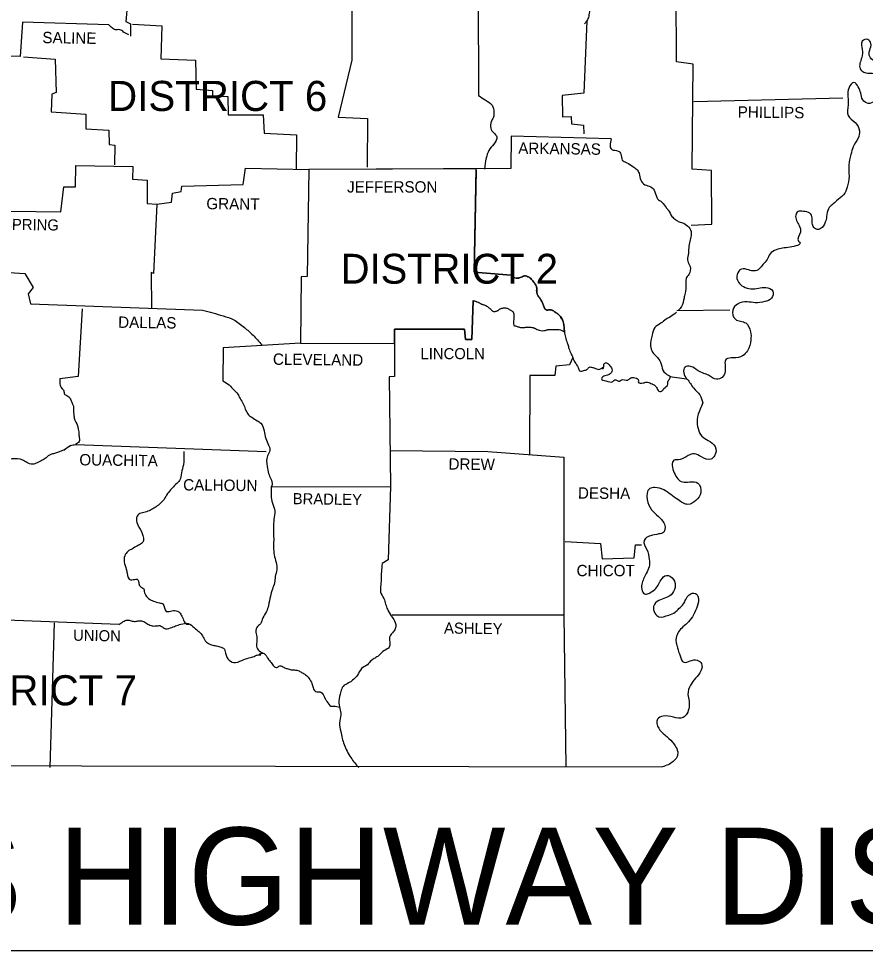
# Model space of a CAD drawing. Extents: x -42408 to 34530, y -43140 to 20491.
# Drawn here: x 2569 to 4174, y -23266 to -21499 of the extents above; entities that cross this region are included whole.
import ezdxf

# ---------------------------------------------------------------- set-up
doc = ezdxf.new("R2010")
doc.units = 0
for name, color, linetype in [('1', 7, 'Continuous'), ('2', 7, 'Continuous'), ('3', 7, 'Continuous'), ('S_MISC_BOUNDARY', 7, 'Continuous')]:
    doc.layers.add(name, color=color, linetype=linetype)

msp = doc.modelspace()

# ---------------------------------------------------------------- linework, layer by layer
at = {"layer": '1'}
msp.add_line((3816.9, -22053), (3917, -22051.5), dxfattribs=at)
for points in [[(3368.8, -21361.6), (3369.8, -21451.2), (3440.4, -21452.7), (3440.9, -21645)], [(3171, -21384.6), (3200.1, -21386.6), (3200.6, -21577.9), (3174.5, -21686.5), (3230.1, -21689), (3229.6, -21781.2)], [(2939.2, -21434.7), (2903.2, -21430.7), (2904.7, -21444.2), (2839.1, -21446.7), (2837.1, -21466.2), (2775.5, -21469.7), (2772, -21504.8), (2781, -21509.3), (2781, -21532.3)], [(3843.9, -21891.3), (3883, -21888.8), (3882.5, -21787.2), (3845.9, -21784.7), (3847.9, -21585.9), (3816.4, -21581.4), (3815.4, -21447.7), (4242.5, -21444.7)], [(2740, -21511.3), (2576.3, -21506.3), (2571.7, -21570.9), (2371.5, -21569.9), (2370.5, -21591.4)], [(2784.5, -21509.8), (2840.6, -21513.3), (2838.6, -21575.9), (2904.2, -21578.4), (2905.2, -21633), (2936.2, -21635.5), (2936.2, -21645), (2965.3, -21647), (2966.3, -21682), (3032.4, -21682), (3034.4, -21716.6), (3095.4, -21719.6), (3094.9, -21784.7)], [(3646.2, -21503.3), (3640.2, -21640.5), (3599.1, -21645), (3600.1, -21685.5), (3616.6, -21685), (3617.1, -21699), (3639.7, -21701.5), (3640.2, -21718.1)], [(2577.8, -21571.9), (2638.3, -21576.4), (2640.3, -21639.5), (2631.8, -21642.5), (2630.8, -21676), (2696.4, -21680.5), (2696.4, -21708.1), (2740, -21710.6), (2740.5, -21738.1), (2751, -21739.6), (2750.5, -21776.6)], [(3848.9, -21656.5), (4131.3, -21649.5)], [(3692.2, -21727.1), (3503, -21722.1), (3502, -21783.7), (3119, -21785.2)], [(2362.5, -21861.8), (2648.8, -21865.8), (2654.4, -21818.2), (2676.9, -21818.2), (2677.4, -21778.1), (2785.5, -21779.7), (2784.5, -21803.7), (2812.6, -21805.7), (2812.6, -21849.7), (2830.6, -21851.2)], [(2830.6, -21851.2), (2858.6, -21847.2), (2860.6, -21830.2), (2877.2, -21827.2), (2878.2, -21817.2), (2994.8, -21813.7), (2999.3, -21783.2), (3119, -21785.2)], [(3119, -21786.2), (3116, -21988.4), (3104.5, -21988.9), (3103, -22114.6)], [(3436.4, -21786.7), (3432.4, -21980.4), (3502, -21985.9)], [(2830.6, -21851.2), (2824.6, -21982.4), (2820.1, -21980.9), (2820.6, -22049)], [(2303.4, -21995.4), (2302.4, -21967.9), (2310.4, -21967.4), (2315.4, -21902.8), (2392.5, -21907.8), (2390.5, -21947.4), (2490.1, -21952.9), (2490.6, -21976.9), (2580.8, -21982.4), (2596.3, -22009.5), (2586.8, -22021.5), (2591.3, -22040), (2917.7, -22052)], [(2689.4, -22049.5), (2681.9, -22178.2), (2647.3, -22182.2)], [(3430.9, -22034), (3427.9, -22107.6), (3416.4, -22107.6), (3414.4, -22088.1), (3281.2, -22088.1), (3281.2, -22116.1)], [(3030.9, -22119.1), (2956.8, -22123.6), (2956.3, -22186.2)], [(3103, -22114.6), (3029.9, -22119.1)], [(3103, -22114.6), (3280.2, -22115.6)], [(3281.2, -22115.6), (3281.7, -22178.2), (3271.2, -22178.7), (3274.2, -22386.5)], [(3619.6, -22142.1), (3613.6, -22155.7), (3587.1, -22158.2), (3585.6, -22176.2), (3538, -22176.2), (3537.5, -22325.9)], [(3675.7, -22164.2), (3677.2, -22162.7), (3678.7, -22161.2), (3678.7, -22161.2)], [(2676.9, -22306.9), (2884.2, -22314.4), (3037.9, -22320.4)], [(3272.7, -22318.4), (3458.4, -22319.9), (3602.6, -22330.9)], [(3602.6, -22330.9), (3602.6, -22630.3), (3606.6, -22918.2)], [(3047.9, -22387), (3274.2, -22386.5)], [(3274.2, -22386.5), (3269.2, -22525.6), (3258.2, -22532.7)], [(3605.1, -22490.6), (3672.2, -22494.6), (3675.2, -22523.6), (3735.8, -22521.6), (3738.3, -22497.1), (3749.8, -22497.1)], [(1953.4, -22510.1), (1954.4, -22915.2), (3789.4, -22918.2)], [(2759, -22648.3), (2545.2, -22640.3), (2544.2, -22589.7)], [(3277.2, -22629.8), (3602.6, -22629.8)], [(2636.3, -22644.8), (2628.3, -22919.7)]]:
    msp.add_lwpolyline(points, dxfattribs=at)
for points in [[(3640.7, -21455.2), (3638.7, -21465.2), (3642.7, -21475.7), (3649.7, -21479.3), (3650.7, -21489.3), (3648.2, -21499.3), (3646.2, -21503.3), (3641.7, -21509.3)], [(2777.5, -21529.8), (2768, -21524.8), (2760.5, -21520.3), (2752.5, -21520.8), (2746, -21516.8), (2740, -21511.3)], [(4210.9, -21565.9), (4199.4, -21580.4), (4182.4, -21571.4), (4182.4, -21559.4), (4184.9, -21546.8), (4178.9, -21538.8), (4168.4, -21542.3), (4168.4, -21557.9), (4167.4, -21572.9), (4164.4, -21594.4), (4171.4, -21600.9), (4187.4, -21602.9), (4198.9, -21605.9), (4205.9, -21617.4), (4205.4, -21631.5), (4199.9, -21645), (4191.9, -21656), (4179.4, -21660), (4169.4, -21653.5), (4165.4, -21640.5), (4160.9, -21628.9), (4152.4, -21620.4), (4143.3, -21630), (4141.3, -21647.5), (4141.8, -21662.5), (4141.8, -21683), (4154.9, -21696.5), (4162.9, -21712.1), (4160.4, -21726.1), (4150.9, -21742.6), (4146.8, -21757.1), (4142.8, -21776.6), (4143.3, -21798.2), (4139.8, -21819.2), (4132.8, -21833.2), (4119.8, -21844.7), (4111.3, -21852.2), (4104.3, -21859.8), (4100.8, -21874.8), (4098.3, -21885.3), (4088.8, -21897.8), (4081.3, -21898.8), (4075.3, -21893.8), (4073.2, -21885.3), (4073.2, -21876.8), (4069.2, -21868.3), (4056.7, -21864.8), (4046.7, -21865.3), (4042.2, -21872.3), (4048.7, -21891.8), (4051.2, -21904.3), (4047.7, -21921.3), (4049.7, -21923.3), (4031.7, -21932.9), (4017.2, -21934.4), (4005.2, -21937.9), (3993.6, -21945.4), (3988.1, -21956.4), (3980.1, -21965.4), (3973.1, -21973.9), (3963.6, -21977.9), (3953.1, -21975.9), (3939.1, -21974.4), (3931.1, -21984.4), (3933.6, -21998.9), (3943.1, -22007.5), (3957.1, -22011.5), (3971.6, -22010.5), (3985.6, -22009), (3998.6, -22016), (3996.1, -22029.5), (3983.6, -22036), (3965.1, -22038), (3950.1, -22036.5), (3932.1, -22040.5), (3923, -22052), (3928.1, -22069.5), (3947.6, -22076.5), (3956.6, -22093.1), (3957.1, -22108.6), (3950.6, -22129.1), (3941.6, -22138.6), (3924, -22142.6), (3910.5, -22145.1), (3908.5, -22168.2), (3902.5, -22179.7), (3892, -22183.2), (3877, -22175.7), (3868, -22172.2), (3857, -22167.2), (3842.9, -22158.7), (3832.4, -22160.2), (3835.4, -22182.2), (3836.4, -22183.2), (3848.4, -22199.7), (3860.5, -22212.7), (3866, -22228.2)], [(3440.9, -21645), (3453.4, -21653.5), (3466.4, -21663.5), (3469.9, -21677), (3468.9, -21686.5), (3464.9, -21694.5), (3463.9, -21707.1), (3469.9, -21716.1), (3475.5, -21723.6), (3469.9, -21737.1), (3460.4, -21749.6), (3455.4, -21763.6), (3451.9, -21784.7)], [(3692.2, -21727.1), (3693.7, -21747.6), (3705.8, -21750.6), (3710.8, -21756.1), (3713.3, -21767.6), (3721.8, -21772.6), (3733.3, -21779.7), (3740.3, -21784.7), (3745.3, -21792.7), (3748.3, -21805.7), (3756.3, -21814.2), (3767.3, -21818.2), (3775.4, -21827.7), (3780.4, -21841.2), (3788.4, -21847.2), (3796.4, -21857.8), (3800.4, -21862.3), (3807.4, -21874.3), (3814.4, -21880.3), (3819.4, -21883.8), (3827.4, -21886.3), (3837.4, -21892.8), (3843.9, -21902.8), (3843.9, -21910.3), (3841.4, -21921.8), (3839.4, -21933.9), (3838.4, -21947.4), (3837.4, -21959.4), (3841.9, -21969.4), (3839.4, -21984.4), (3834.4, -21992.4), (3833.9, -22003.4), (3832.4, -22020), (3830.4, -22029.5), (3825.9, -22045), (3819.4, -22053)], [(3502, -21985.9), (3509.5, -21990.9), (3520, -21990.4), (3527, -21987.4), (3532.5, -21987.9), (3540, -21992.4), (3545, -21998.4), (3548.5, -22002.9), (3551.1, -22010), (3551.1, -22016.5), (3553.6, -22025.5), (3556.6, -22029), (3560.6, -22035.5), (3563.1, -22041.5), (3564.6, -22045.5), (3570.1, -22052), (3575.1, -22051.5), (3579.6, -22052), (3585.6, -22055.5), (3594.6, -22062.5), (3596.1, -22064.5), (3602.1, -22077.5), (3603.1, -22085.6), (3604.1, -22096.1), (3606.1, -22106.1), (3610.1, -22117.1), (3612.1, -22124.6), (3616.6, -22135.1), (3619.6, -22142.1), (3623.6, -22151.1), (3629.7, -22161.2), (3632.2, -22167.2), (3640.7, -22166.7), (3646.7, -22164.2), (3651.2, -22160.2), (3656.7, -22160.7), (3662.7, -22162.7), (3670.7, -22164.2), (3675.7, -22161.2), (3678.2, -22159.2), (3678.7, -22154.7), (3683.2, -22152.1), (3688.2, -22155.7), (3693.7, -22163.7), (3693.7, -22168.7), (3691.7, -22171.7), (3685.2, -22175.7), (3676.2, -22178.7), (3673.7, -22182.2), (3682.2, -22186.2), (3695.7, -22187.2), (3699.2, -22184.2), (3708.3, -22186.7), (3711.8, -22184.2), (3723.8, -22184.7), (3729.3, -22180.7), (3740.3, -22181.2), (3743.8, -22183.7), (3743.8, -22188.2), (3752.8, -22190.2), (3759.3, -22188.7), (3767.8, -22191.2), (3775.4, -22195.2), (3779.4, -22200.7), (3784.4, -22206.7), (3788.9, -22205.2), (3792.4, -22200.7), (3799.9, -22192.7), (3799.9, -22187.7), (3801.9, -22184.2), (3804.4, -22179.2)], [(2917.7, -22052), (2956.8, -22063), (2976.8, -22070.5), (2996.8, -22085.1), (3013.3, -22099.6), (3029.9, -22118.1)], [(3815.9, -22056), (3805.4, -22064.5), (3796.4, -22069.5), (3786.9, -22076.5), (3775.4, -22085.1), (3769.8, -22099.6), (3766.8, -22119.6), (3770.8, -22131.6), (3779.9, -22142.1), (3785.9, -22150.6), (3790.4, -22165.7), (3801.4, -22176.2), (3804.9, -22177.7)], [(2647.3, -22182.2), (2647.3, -22191.7), (2650.9, -22200.7), (2654.4, -22204.7), (2655.9, -22211.2), (2660.4, -22214.2), (2666.9, -22220.2), (2670.4, -22228.8), (2672.9, -22234.3), (2672.9, -22241.3), (2673.4, -22248.3), (2674.4, -22256.8), (2680.4, -22271.8), (2681.9, -22277.8), (2682.9, -22282.8), (2683.4, -22291.3), (2683.4, -22301.3), (2676.9, -22306.9)], [(2956.3, -22186.2), (2967.8, -22193.7), (2977.3, -22203.7), (2984.3, -22211.2), (2988.8, -22219.7), (2994.8, -22229.8), (3003.3, -22248.8), (3010.8, -22255.3), (3021.3, -22261.8), (3027.9, -22266.3), (3034.4, -22280.8), (3037.4, -22295.3), (3042.9, -22308.4), (3045.4, -22318.4), (3040.9, -22328.4), (3039.9, -22348.4), (3042.9, -22361.9), (3046.9, -22371.9), (3049.4, -22383.5), (3047.9, -22387)], [(3866, -22228.2), (3861, -22239.8), (3855.5, -22259.8), (3857, -22276.8), (3864.5, -22291.3), (3876.5, -22299.3), (3889.5, -22310.9), (3888.5, -22328.4), (3881, -22334.9), (3863.5, -22330.4), (3850, -22324.4), (3838.4, -22327.9), (3822.9, -22335.4), (3811.4, -22336.9), (3811.9, -22360.9), (3827.4, -22377.9), (3840.9, -22377.9), (3856.5, -22380), (3862, -22398), (3853, -22413), (3837.9, -22420.5), (3818.9, -22411.5), (3805.4, -22402), (3791.9, -22393), (3774.9, -22388.5), (3765.3, -22390.5), (3760.8, -22411.5), (3768.8, -22430.5), (3781.9, -22443.5), (3793.9, -22460.6), (3791.9, -22473.1), (3782.9, -22476.6), (3766.8, -22480.1), (3757.3, -22485.1), (3754.8, -22489.1), (3759.8, -22506.1), (3764.3, -22524.6), (3764.3, -22538.7), (3758.8, -22551.7), (3750.3, -22571.7), (3751.3, -22584.7), (3757.3, -22590.7), (3764.8, -22588.7), (3774.9, -22581.7), (3781.4, -22573.7), (3786.9, -22563.7), (3797.4, -22555.2), (3810.4, -22562.7), (3813.4, -22578.2), (3805.9, -22591.7), (3795.4, -22597.7), (3782.4, -22602.7), (3772.8, -22613.8), (3775.4, -22626.8), (3782.9, -22633.8), (3801.4, -22630.3), (3813.9, -22624.8), (3820.9, -22617.8), (3829.4, -22609.3), (3833.9, -22600.7), (3840.4, -22591.7), (3852, -22589.2), (3857.5, -22596.7), (3855.5, -22613.8), (3848.4, -22629.8), (3838.9, -22643.3), (3828.4, -22652.8), (3815.4, -22673.3), (3817.9, -22692.4), (3822.9, -22707.9), (3829.9, -22719.9), (3841.9, -22717.4), (3855.5, -22715.9), (3863.5, -22722.4), (3862.5, -22736.4), (3852.5, -22749.9), (3842.9, -22763), (3837.9, -22781), (3839.9, -22793.5), (3839.9, -22805), (3835.9, -22817.5), (3828.9, -22824.5), (3810.4, -22824), (3790.9, -22822), (3780.4, -22828), (3782.4, -22845.1), (3793.9, -22857.6), (3801.9, -22864.1), (3813.4, -22878.1), (3818.4, -22889.6), (3816.9, -22899.6), (3809.9, -22908.2), (3789.4, -22918.2)], [(2667.4, -22308.9), (2654.4, -22317.4), (2644.3, -22321.4), (2636.8, -22323.9), (2629.8, -22325.9), (2620.8, -22331.9), (2613.8, -22336.9), (2604.3, -22341.4), (2595.3, -22344.4), (2584.3, -22340.9), (2578.3, -22337.4), (2571.7, -22334.9), (2550.7, -22334.9)], [(2654.4, -22317.4), (2667.4, -22308.9), (2676.9, -22306.9)], [(2882.2, -22320.4), (2881.2, -22345.4), (2877.7, -22360.9), (2874.1, -22374.9), (2866.6, -22383), (2858.6, -22391), (2851.1, -22400), (2844.6, -22411), (2838.1, -22418), (2829.6, -22425), (2821.1, -22430), (2811.6, -22434.5), (2801.1, -22437), (2793.5, -22442.5), (2793, -22454.6), (2801.6, -22471.6), (2804.6, -22479.6), (2805.6, -22489.1), (2802.1, -22494.6), (2794, -22499.1), (2784.5, -22504.6), (2776, -22509.6), (2770, -22518.1), (2769, -22529.7), (2773, -22543.2), (2774.5, -22551.2), (2781, -22563.7), (2786, -22563.2), (2795, -22563.7), (2796, -22566.2), (2796.5, -22568.7), (2798.5, -22575.2), (2806.1, -22580.7), (2807.1, -22585.7), (2811.6, -22595.2), (2819.1, -22601.7), (2824.6, -22603.8), (2836.1, -22607.3), (2842.1, -22608.8), (2848.6, -22623.3), (2856.6, -22622.8), (2862.6, -22621.8), (2872.6, -22624.3), (2877.2, -22630.3), (2881.7, -22640.3), (2887.7, -22647.3), (2891.7, -22647.3)], [(3047.9, -22387), (3049.9, -22418), (3054.4, -22433), (3052.9, -22449), (3052.4, -22464.6), (3052.4, -22478.6), (3052.4, -22492.1), (3052.4, -22506.1), (3053.4, -22516.1), (3056.9, -22530.7), (3058.4, -22544.2), (3055.4, -22557.2), (3053.9, -22569.2), (3049.9, -22581.2), (3046.4, -22594.7), (3042.4, -22612.3), (3038.9, -22623.8), (3031.9, -22635.8), (3027.4, -22646.8), (3020.3, -22653.8), (3019.3, -22665.8), (3020.8, -22676.8), (3019.8, -22686.9), (3023.3, -22696.4), (3032.4, -22702.9)], [(3258.2, -22532.7), (3256.7, -22548.2), (3256.2, -22562.7), (3255.2, -22576.7), (3255.2, -22587.2), (3261.2, -22598.7), (3264.7, -22609.8), (3268.2, -22619.3), (3275.2, -22631.8), (3281.7, -22641.3), (3283.7, -22654.8), (3279.7, -22661.8), (3272.2, -22672.3), (3271.7, -22691.4), (3262.7, -22697.4), (3251.2, -22707.4), (3244.6, -22711.9), (3237.6, -22716.4), (3230.1, -22724.4), (3219.1, -22731.9), (3211.1, -22744.4), (3202.1, -22754), (3194.6, -22759), (3184.1, -22765.5), (3179.6, -22775.5), (3176.1, -22794), (3177.6, -22807.5), (3179.6, -22819.5), (3177.1, -22834.6), (3179.6, -22851.1), (3182.1, -22864.1), (3186.1, -22875.6), (3191.6, -22888.6), (3198.6, -22900.6), (3213.6, -22919.2)], [(2759, -22648.3), (2767, -22642.8), (2774.5, -22639.8), (2782, -22641.3), (2790, -22642.3), (2797, -22641.3), (2806.1, -22642.8), (2813.6, -22647.3), (2822.1, -22650.8), (2830.6, -22650.8), (2838.1, -22650.8), (2844.6, -22655.3), (2856.6, -22654.8), (2866.6, -22650.8), (2876.7, -22647.8), (2890.2, -22646.3), (2902.2, -22654.8), (2910.7, -22661.8), (2917.7, -22669.8), (2922.7, -22678.9), (2928.2, -22683.9), (2937.2, -22687.4), (2944.2, -22688.9), (2952.8, -22691.4), (2957.3, -22693.4), (2961.3, -22702.9), (2967.8, -22715.9), (2980.3, -22720.4), (2995.8, -22714.4), (3008.3, -22710.9), (3017.3, -22707.9), (3022.8, -22705.9), (3027.9, -22705.4), (3026.4, -22704.4), (3032.4, -22702.9), (3037.9, -22706.9), (3041.4, -22712.4), (3047.4, -22720.4), (3052.9, -22727.4), (3058.4, -22729.9), (3063.9, -22726.9), (3071.4, -22729.4), (3077.9, -22731.9), (3085.4, -22733.9), (3091.9, -22734.4), (3100.5, -22736.4), (3107, -22739.9), (3113, -22743.4), (3119, -22749.9), (3125, -22760), (3127, -22768), (3134, -22776), (3140.5, -22776), (3150, -22789), (3153.5, -22794), (3161, -22803), (3166.5, -22803), (3177.1, -22805)]]:
    msp.add_spline(points, degree=3, dxfattribs=at)
at = {"layer": '2'}
msp.add_line((1233.5, -23266.2), (4582.8, -23266.2), dxfattribs=at)
at = {"layer": '3'}
msp.add_line((3803.4, -22178.2), (3834.9, -22182.2), dxfattribs=at)
at = {"layer": 'S_MISC_BOUNDARY'}
for p, q in [((3436.5, -21783.9), (3119, -21785.2)), ((3103, -22114.6), (3281.2, -22115.6))]:
    msp.add_line(p, q, dxfattribs=at)
for points in [[(3502, -21985.9), (3432.4, -21980.4), (3436.5, -21783.9)], [(3119, -21785.2), (3116, -21988.4), (3104.5, -21988.9), (3103, -22114.6)], [(3281.2, -22115.6), (3281.2, -22088.1), (3414.4, -22088.1), (3416.4, -22107.6), (3427.9, -22107.6), (3430.9, -22034)]]:
    msp.add_lwpolyline(points, dxfattribs=at)
for points in [[(3558, -22031.1), (3556.6, -22029), (3555.8, -22028.1), (3555, -22027.3), (3554.2, -22026.4), (3553.6, -22025.5), (3551.8, -22021.1), (3551.1, -22016.5), (3551, -22014.8), (3551.1, -22013.2), (3551.2, -22011.6), (3551.1, -22010), (3550.7, -22008.1), (3550.2, -22006.3), (3548.5, -22002.9), (3545, -21998.4), (3540, -21992.4), (3536.6, -21989.8), (3534.6, -21988.8), (3532.5, -21987.9), (3529.8, -21987.3), (3528.4, -21987.3), (3527, -21987.4), (3525.2, -21988), (3523.5, -21988.9), (3521.8, -21989.8), (3520, -21990.4), (3514.8, -21991.4), (3512.1, -21991.4), (3509.5, -21990.9), (3507.4, -21990.1), (3505.5, -21988.9), (3502, -21985.9)], [(3603.9, -22093.7), (3603.1, -22085.6), (3602.7, -22081.5), (3602.4, -22079.5), (3602.1, -22077.5), (3599.8, -22070.8), (3598, -22067.7), (3596.1, -22064.5), (3594.6, -22062.5), (3593.6, -22061.5), (3592.5, -22060.6), (3590.3, -22058.8), (3585.6, -22055.5), (3582.7, -22053.6), (3581.2, -22052.7), (3580.4, -22052.4), (3579.6, -22052), (3577.3, -22051.6), (3575.1, -22051.5), (3573.8, -22051.6), (3572.6, -22052), (3571.3, -22052.2), (3570.1, -22052), (3569.1, -22051.5), (3568.2, -22050.9), (3566.7, -22049.4), (3566.1, -22048.4), (3565.5, -22047.5), (3564.6, -22045.5), (3563.1, -22041.5), (3560.6, -22035.5), (3558.7, -22032.2), (3558, -22031.1)], [(3430.9, -22034), (3433.2, -22034.5), (3435.5, -22035.2), (3439.9, -22037), (3441.6, -22037.8), (3443.2, -22038.8), (3444.8, -22039.7), (3446.4, -22040.5), (3448.5, -22041.3), (3450.7, -22041.9), (3452.9, -22042.6), (3454.9, -22043.5), (3457.7, -22045.4), (3460.4, -22047.5), (3462.3, -22049.1), (3464.1, -22050.8), (3466, -22052.5), (3466.9, -22053.3), (3467.9, -22054), (3470, -22054.7), (3472.4, -22054.6), (3474.7, -22053.9), (3477, -22053), (3478.6, -22052.1), (3480.1, -22050.9), (3481.7, -22049.8), (3483.5, -22049), (3490, -22048), (3493.6, -22048.1)], [(3493.6, -22048.1), (3495, -22048.5), (3500.5, -22051.5), (3501.3, -22052), (3503.8, -22053.4), (3505.2, -22054.5), (3505.9, -22055.2), (3506.2, -22055.6), (3506.5, -22056), (3507.5, -22059.2), (3507.5, -22060.9), (3507.5, -22062.5), (3507.5, -22070), (3507.5, -22080.6), (3507.9, -22081.3), (3508.8, -22081.6), (3510.5, -22081.9), (3511, -22082.1), (3514.1, -22083), (3517.2, -22084), (3523.5, -22085.1), (3525.6, -22085), (3527.8, -22084.9), (3529.9, -22084.7), (3532, -22084.6), (3536, -22084.5), (3536.5, -22084.5)], [(3536.5, -22084.5), (3540, -22084.6), (3543.3, -22085.1), (3544.9, -22085.5), (3546.5, -22086.1), (3548, -22086.7), (3549.3, -22087.6), (3550.6, -22088.4), (3552.1, -22089.1), (3556.1, -22090.1), (3562.1, -22091.1), (3567.1, -22090.6), (3569.2, -22090), (3571.3, -22089.4), (3573.4, -22088.8), (3575.6, -22088.6), (3580.6, -22088.6), (3588.6, -22088.6), (3591.1, -22088.7), (3592.4, -22088.9), (3593.6, -22089.1), (3599, -22090.7), (3603.9, -22093.7)]]:
    msp.add_spline(points, degree=3, dxfattribs=at)

# ---------------------------------------------------------------- texts
at = {"layer": '2'}
for s, height, rotation, p in [('SALINE', 21.53, 359.1491, (2613.8, -21545.8)), ('PHILLIPS', 21.52, 359.3179, (3932.1, -21687)), ('ARKANSAS', 21.52, 359.2678, (3516, -21755.6)), ('GRANT', 21.53, 359.4032, (2924.7, -21860.8)), ('HOT SPRING', 21.03, 359.2216, (2470.1, -21898.8)), ('DALLAS', 21.52, 359.2462, (2757.5, -22085.6)), ('CLEVELAND', 21.53, 359.3377, (3050.9, -22155.7)), ('OUACHITA', 21.53, 359.2043, (2683.9, -22346.4)), ('DREW', 21.52, 359.2258, (3383.8, -22354.4)), ('CALHOUN', 21.53, 359.3634, (2880.7, -22394)), ('BRADLEY', 21.02, 359.1449, (3088.4, -22420)), ('DESHA', 21.52, 359.3704, (3629.2, -22409.5)), ('ASHLEY', 21.03, 359.2361, (3375.3, -22665.3)), ('UNION', 21.03, 358.9584, (2671.9, -22678.9))]:
    msp.add_text(s, height=height, rotation=rotation, dxfattribs=at).set_placement(p)
for s, height, p in [('JEFFERSON', 21.53, (3191.6, -21829.2)), ('LINCOLN', 21.03, (3330.8, -22145.1)), ('CHICOT', 21.53, (3626.7, -22556.7)), ('ARKANSAS HIGHWAY DISTRICT 2', 184.218, (1233.5, -23217.5))]:
    msp.add_text(s, height=height, dxfattribs=at).set_placement(p)
at = {"layer": '3'}
for s, height, p in [('DISTRICT 6', 57.08, (2738.5, -21674.5)), ('DISTRICT 2', 56.57, (3179.6, -22001.9)), ('DISTRICT 7', 57.08, (2377.5, -22801.5))]:
    msp.add_text(s, height=height, dxfattribs=at).set_placement(p)

doc.saveas('drawing.dxf')
